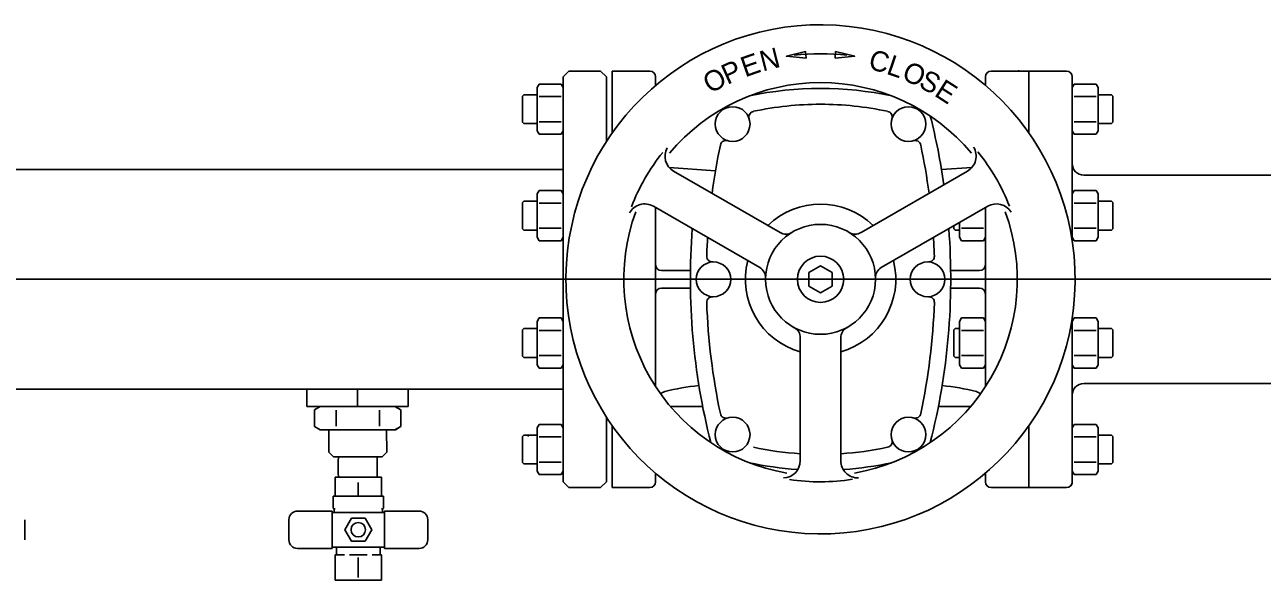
# Model space of a CAD drawing. Extents: x 6710407 to 6714861, y 1868090 to 1871317.
# Drawn here: x 6713875.1 to 6713934, y 1869959.7 to 1869986.1 of the extents above; entities that cross this region are included whole.
import ezdxf

# ---------------------------------------------------------------- set-up
doc = ezdxf.new("R2010")
doc.units = 0
doc.layers.add('Nongeo Data(60)', color=7, linetype='Continuous')

msp = doc.modelspace()

# ---------------------------------------------------------------- linework, layer by layer
at = {"layer": 'Nongeo Data(60)'}
for p, q in [((6713900.993, 1869983.89), (6713900.717, 1869983.614)), ((6713900.717, 1869983.614), (6713900.717, 1869979.484)), ((6713902.507, 1869983.89), (6713900.993, 1869983.89)), ((6713902.507, 1869983.89), (6713902.782, 1869983.614)), ((6713902.782, 1869980.534), (6713902.782, 1869983.614)), ((6713903.057, 1869983.89), (6713904.847, 1869983.89)), ((6713903.057, 1869980.943), (6713903.057, 1869983.89)), ((6713903.057, 1869983.89), (6713903.057, 1869980.943)), ((6713905.122, 1869983.207), (6713905.122, 1869983.614)), ((6713920.816, 1869983.614), (6713920.816, 1869983.207)), ((6713922.364, 1869983.891), (6713921.091, 1869983.891)), ((6713922.881, 1869983.89), (6713921.091, 1869983.89)), ((6713922.881, 1869983.89), (6713922.881, 1869980.943)), ((6713922.881, 1869983.89), (6713922.881, 1869980.943)), ((6713922.881, 1869983.89), (6713924.67, 1869983.89)), ((6713924.946, 1869983.614), (6713924.946, 1869975.799)), ((6713899.576, 1869983.268), (6713899.484, 1869983.108)), ((6713899.484, 1869981.043), (6713899.484, 1869983.108)), ((6713899.576, 1869983.268), (6713900.625, 1869983.268)), ((6713900.625, 1869983.268), (6713900.717, 1869983.108)), ((6713900.717, 1869981.043), (6713900.717, 1869983.108)), ((6713920.816, 1869983.268), (6713920.744, 1869983.268)), ((6713925.038, 1869983.268), (6713924.946, 1869983.108)), ((6713924.946, 1869983.108), (6713924.946, 1869981.043)), ((6713926.087, 1869983.268), (6713925.038, 1869983.268)), ((6713926.087, 1869983.268), (6713926.179, 1869983.108)), ((6713926.179, 1869983.108), (6713926.179, 1869981.043)), ((6713898.79, 1869982.698), (6713898.856, 1869982.764)), ((6713898.79, 1869981.453), (6713898.79, 1869982.698)), ((6713898.856, 1869982.764), (6713899.484, 1869982.764)), ((6713899.579, 1869982.672), (6713900.622, 1869982.672)), ((6713926.084, 1869982.672), (6713925.04, 1869982.672)), ((6713926.806, 1869982.764), (6713926.179, 1869982.764)), ((6713926.873, 1869982.698), (6713926.806, 1869982.764)), ((6713926.873, 1869982.698), (6713926.873, 1869981.453)), ((6713898.79, 1869981.453), (6713898.856, 1869981.387)), ((6713898.856, 1869981.387), (6713899.484, 1869981.387)), ((6713899.579, 1869981.48), (6713900.622, 1869981.48)), ((6713926.084, 1869981.48), (6713925.04, 1869981.48)), ((6713926.806, 1869981.387), (6713926.179, 1869981.387)), ((6713926.873, 1869981.453), (6713926.806, 1869981.387)), ((6713899.576, 1869980.883), (6713899.484, 1869981.043)), ((6713899.576, 1869980.883), (6713900.625, 1869980.883)), ((6713900.625, 1869980.883), (6713900.717, 1869981.043)), ((6713925.038, 1869980.883), (6713924.946, 1869981.043)), ((6713926.087, 1869980.883), (6713925.038, 1869980.883)), ((6713926.087, 1869980.883), (6713926.179, 1869981.043)), ((6713900.717, 1869973.978), (6713900.717, 1869979.484)), ((6713843.175, 1869979.209), (6713899.454, 1869979.209)), ((6713899.454, 1869979.209), (6713900.717, 1869979.209)), ((6713907.969, 1869979.148), (6713905.767, 1869979.302)), ((6713911.043, 1869976.203), (6713905.98, 1869979.126)), ((6713914.895, 1869976.203), (6713919.958, 1869979.126)), ((6713918.728, 1869979.201), (6713920.171, 1869979.302)), ((6713925.496, 1869978.934), (6713931.613, 1869978.934)), ((6713931.613, 1869978.934), (6713949.736, 1869978.934)), ((6713898.79, 1869977.632), (6713898.856, 1869977.698)), ((6713898.79, 1869976.387), (6713898.79, 1869977.632)), ((6713898.856, 1869977.698), (6713899.484, 1869977.698)), ((6713899.576, 1869978.202), (6713899.484, 1869978.042)), ((6713899.484, 1869975.977), (6713899.484, 1869978.042)), ((6713899.576, 1869978.202), (6713900.625, 1869978.202)), ((6713900.625, 1869978.202), (6713900.717, 1869978.042)), ((6713900.717, 1869975.977), (6713900.717, 1869978.042)), ((6713925.038, 1869978.202), (6713924.946, 1869978.042)), ((6713924.946, 1869978.042), (6713924.946, 1869975.977)), ((6713926.087, 1869978.202), (6713925.038, 1869978.202)), ((6713926.087, 1869978.202), (6713926.179, 1869978.042)), ((6713926.179, 1869978.042), (6713926.179, 1869975.977)), ((6713926.806, 1869977.698), (6713926.179, 1869977.698)), ((6713926.873, 1869977.632), (6713926.806, 1869977.698)), ((6713926.873, 1869977.632), (6713926.873, 1869976.387)), ((6713899.579, 1869977.606), (6713900.622, 1869977.606)), ((6713910.079, 1869974.534), (6713905.016, 1869977.457)), ((6713905.122, 1869968.873), (6713905.122, 1869977.396)), ((6713915.859, 1869974.534), (6713920.922, 1869977.457)), ((6713920.816, 1869968.873), (6713920.816, 1869977.396)), ((6713920.816, 1869975.977), (6713920.816, 1869977.396)), ((6713926.084, 1869977.606), (6713925.04, 1869977.606)), ((6713919.307, 1869976.387), (6713919.307, 1869976.524)), ((6713919.582, 1869975.977), (6713919.582, 1869976.683)), ((6713898.79, 1869976.387), (6713898.856, 1869976.321)), ((6713898.856, 1869976.321), (6713899.484, 1869976.321)), ((6713899.576, 1869975.817), (6713899.484, 1869975.977)), ((6713899.579, 1869976.414), (6713900.622, 1869976.414)), ((6713900.625, 1869975.817), (6713900.717, 1869975.977)), ((6713919.307, 1869976.387), (6713919.373, 1869976.321)), ((6713919.373, 1869976.321), (6713919.582, 1869976.321)), ((6713919.675, 1869975.817), (6713919.582, 1869975.977)), ((6713919.677, 1869976.413), (6713920.721, 1869976.413)), ((6713920.723, 1869975.817), (6713920.816, 1869975.977)), ((6713925.038, 1869975.817), (6713924.946, 1869975.977)), ((6713926.084, 1869976.414), (6713925.04, 1869976.414)), ((6713926.087, 1869975.817), (6713926.179, 1869975.977)), ((6713926.806, 1869976.321), (6713926.179, 1869976.321)), ((6713926.873, 1869976.387), (6713926.806, 1869976.321)), ((6713899.576, 1869975.817), (6713900.625, 1869975.817)), ((6713919.675, 1869975.817), (6713920.723, 1869975.817)), ((6713926.087, 1869975.817), (6713925.038, 1869975.817)), ((6713906.777, 1869974.391), (6713905.398, 1869974.391)), ((6713919.161, 1869974.391), (6713920.54, 1869974.391)), ((6713748.2, 1869973.985), (6713995.625, 1869973.985)), ((6713900.717, 1869964.342), (6713900.717, 1869973.978)), ((6713906.777, 1869973.565), (6713905.398, 1869973.565)), ((6713919.161, 1869973.565), (6713920.54, 1869973.565)), ((6713899.576, 1869972.139), (6713899.484, 1869971.979)), ((6713899.484, 1869969.914), (6713899.484, 1869971.979)), ((6713899.576, 1869972.139), (6713900.625, 1869972.139)), ((6713900.625, 1869972.139), (6713900.717, 1869971.979)), ((6713900.717, 1869969.914), (6713900.717, 1869971.979)), ((6713919.675, 1869972.139), (6713919.582, 1869971.979)), ((6713919.582, 1869971.979), (6713919.582, 1869969.914)), ((6713919.675, 1869972.139), (6713920.723, 1869972.139)), ((6713920.723, 1869972.139), (6713920.816, 1869971.979)), ((6713920.816, 1869971.979), (6713920.816, 1869969.914)), ((6713924.946, 1869972.157), (6713924.946, 1869964.342)), ((6713925.038, 1869972.139), (6713924.946, 1869971.979)), ((6713924.946, 1869971.979), (6713924.946, 1869969.914)), ((6713926.087, 1869972.139), (6713925.038, 1869972.139)), ((6713926.087, 1869972.139), (6713926.179, 1869971.979)), ((6713926.179, 1869971.979), (6713926.179, 1869969.914)), ((6713898.79, 1869971.569), (6713898.856, 1869971.635)), ((6713898.79, 1869970.324), (6713898.79, 1869971.569)), ((6713898.856, 1869971.635), (6713899.484, 1869971.635)), ((6713899.579, 1869971.542), (6713900.622, 1869971.542)), ((6713912.005, 1869971.197), (6713912.005, 1869965.351)), ((6713913.933, 1869971.197), (6713913.933, 1869965.351)), ((6713919.307, 1869971.569), (6713919.373, 1869971.635)), ((6713919.307, 1869971.569), (6713919.307, 1869970.324)), ((6713919.373, 1869971.635), (6713919.582, 1869971.635)), ((6713919.677, 1869971.542), (6713920.721, 1869971.542)), ((6713926.084, 1869971.542), (6713925.04, 1869971.542)), ((6713926.806, 1869971.635), (6713926.179, 1869971.635)), ((6713926.873, 1869971.568), (6713926.806, 1869971.635)), ((6713926.873, 1869971.568), (6713926.873, 1869970.324)), ((6713898.79, 1869970.324), (6713898.856, 1869970.258)), ((6713898.856, 1869970.258), (6713899.484, 1869970.258)), ((6713899.579, 1869970.35), (6713900.622, 1869970.35)), ((6713919.307, 1869970.324), (6713919.373, 1869970.258)), ((6713919.373, 1869970.258), (6713919.582, 1869970.258)), ((6713919.677, 1869970.35), (6713920.721, 1869970.35)), ((6713926.084, 1869970.35), (6713925.04, 1869970.35)), ((6713926.806, 1869970.258), (6713926.179, 1869970.258)), ((6713926.873, 1869970.324), (6713926.806, 1869970.258)), ((6713899.576, 1869969.754), (6713899.484, 1869969.914)), ((6713899.576, 1869969.754), (6713900.625, 1869969.754)), ((6713900.625, 1869969.754), (6713900.717, 1869969.914)), ((6713919.675, 1869969.754), (6713919.582, 1869969.914)), ((6713919.675, 1869969.754), (6713920.723, 1869969.754)), ((6713920.723, 1869969.754), (6713920.816, 1869969.914)), ((6713925.038, 1869969.754), (6713924.946, 1869969.914)), ((6713926.087, 1869969.754), (6713925.038, 1869969.754)), ((6713926.087, 1869969.754), (6713926.179, 1869969.914)), ((6713925.496, 1869969.022), (6713931.613, 1869969.022)), ((6713931.613, 1869969.022), (6713949.736, 1869969.022)), ((6713843.175, 1869968.747), (6713899.454, 1869968.747)), ((6713888.532, 1869967.921), (6713888.532, 1869968.747)), ((6713890.941, 1869967.921), (6713890.941, 1869968.747)), ((6713893.35, 1869967.921), (6713893.35, 1869968.747)), ((6713899.454, 1869968.747), (6713900.717, 1869968.747)), ((6713888.532, 1869967.921), (6713893.35, 1869967.921)), ((6713888.884, 1869967.761), (6713889.161, 1869967.921)), ((6713888.884, 1869967.761), (6713888.884, 1869966.98)), ((6713889.917, 1869967.757), (6713889.917, 1869966.984)), ((6713891.983, 1869967.757), (6713891.983, 1869966.984)), ((6713892.998, 1869967.761), (6713892.721, 1869967.921)), ((6713892.998, 1869967.761), (6713892.998, 1869966.98)), ((6713907.362, 1869967.921), (6713905.832, 1869967.921)), ((6713918.576, 1869967.921), (6713920.106, 1869967.921)), ((6713899.576, 1869967.072), (6713899.484, 1869966.913)), ((6713899.576, 1869967.072), (6713900.625, 1869967.072)), ((6713900.625, 1869967.072), (6713900.717, 1869966.913)), ((6713902.782, 1869967.422), (6713902.782, 1869964.342)), ((6713925.038, 1869967.072), (6713924.946, 1869966.912)), ((6713926.087, 1869967.072), (6713925.038, 1869967.072)), ((6713926.087, 1869967.072), (6713926.179, 1869966.912)), ((6713888.884, 1869966.98), (6713889.161, 1869966.82)), ((6713889.161, 1869966.82), (6713892.739, 1869966.82)), ((6713889.161, 1869966.82), (6713892.739, 1869966.82)), ((6713889.575, 1869965.75), (6713889.575, 1869966.82)), ((6713892.326, 1869965.75), (6713892.325, 1869966.82)), ((6713892.998, 1869966.98), (6713892.721, 1869966.82)), ((6713892.868, 1869966.894), (6713892.739, 1869966.82)), ((6713898.79, 1869966.503), (6713898.856, 1869966.569)), ((6713898.79, 1869965.258), (6713898.79, 1869966.503)), ((6713898.856, 1869966.569), (6713899.484, 1869966.569)), ((6713899.044, 1869966.503), (6713899.111, 1869966.569)), ((6713899.484, 1869964.848), (6713899.484, 1869966.913)), ((6713899.579, 1869966.476), (6713900.622, 1869966.476)), ((6713900.717, 1869964.848), (6713900.717, 1869966.913)), ((6713903.057, 1869964.066), (6713903.057, 1869967.013)), ((6713903.057, 1869967.013), (6713903.057, 1869964.066)), ((6713922.881, 1869967.013), (6713922.881, 1869964.066)), ((6713922.881, 1869967.013), (6713922.881, 1869964.066)), ((6713924.946, 1869966.912), (6713924.946, 1869964.848)), ((6713926.084, 1869966.476), (6713925.04, 1869966.476)), ((6713926.179, 1869966.912), (6713926.179, 1869964.848)), ((6713926.806, 1869966.569), (6713926.179, 1869966.569)), ((6713926.873, 1869966.502), (6713926.806, 1869966.569)), ((6713926.873, 1869966.502), (6713926.873, 1869965.258)), ((6713889.794, 1869965.531), (6713889.575, 1869965.75)), ((6713889.794, 1869965.531), (6713892.107, 1869965.531)), ((6713890.025, 1869965.325), (6713890.031, 1869965.531)), ((6713890.025, 1869964.774), (6713890.025, 1869965.325)), ((6713891.875, 1869965.325), (6713891.869, 1869965.531)), ((6713891.875, 1869964.774), (6713891.875, 1869965.325)), ((6713892.107, 1869965.531), (6713892.326, 1869965.75)), ((6713899.579, 1869965.284), (6713900.622, 1869965.284)), ((6713926.084, 1869965.284), (6713925.04, 1869965.284)), ((6713890.025, 1869964.774), (6713890.031, 1869964.567)), ((6713891.875, 1869964.774), (6713891.869, 1869964.567)), ((6713898.79, 1869965.258), (6713898.856, 1869965.192)), ((6713898.856, 1869965.192), (6713899.484, 1869965.192)), ((6713899.576, 1869964.688), (6713899.484, 1869964.848)), ((6713899.576, 1869964.688), (6713900.625, 1869964.688)), ((6713900.625, 1869964.688), (6713900.717, 1869964.848)), ((6713905.122, 1869964.342), (6713905.122, 1869964.749)), ((6713920.816, 1869964.688), (6713920.744, 1869964.688)), ((6713920.816, 1869964.342), (6713920.816, 1869964.749)), ((6713925.038, 1869964.688), (6713924.946, 1869964.848)), ((6713926.087, 1869964.688), (6713925.038, 1869964.688)), ((6713926.087, 1869964.688), (6713926.179, 1869964.848)), ((6713926.806, 1869965.192), (6713926.179, 1869965.192)), ((6713926.873, 1869965.258), (6713926.806, 1869965.192)), ((6713890.977, 1869964.567), (6713889.876, 1869964.567)), ((6713889.876, 1869963.664), (6713889.876, 1869964.567)), ((6713889.919, 1869964.456), (6713889.919, 1869964.456)), ((6713890.977, 1869964.567), (6713892.078, 1869964.567)), ((6713890.977, 1869964.316), (6713890.977, 1869963.664)), ((6713891.769, 1869964.456), (6713891.769, 1869964.456)), ((6713892.078, 1869963.664), (6713892.078, 1869964.567)), ((6713900.993, 1869964.066), (6713900.717, 1869964.342)), ((6713902.782, 1869964.342), (6713902.507, 1869964.066)), ((6713892.179, 1869963.664), (6713889.776, 1869963.664)), ((6713889.776, 1869963.664), (6713889.776, 1869963.112)), ((6713892.078, 1869963.664), (6713892.078, 1869963.805)), ((6713892.179, 1869963.664), (6713892.179, 1869963.112)), ((6713902.507, 1869964.066), (6713900.993, 1869964.066)), ((6713903.057, 1869964.066), (6713904.847, 1869964.066)), ((6713922.881, 1869964.066), (6713921.091, 1869964.066)), ((6713922.881, 1869964.066), (6713924.67, 1869964.066)), ((6713889.738, 1869962.954), (6713888.086, 1869962.954)), ((6713889.738, 1869962.062), (6713889.738, 1869962.954)), ((6713889.876, 1869963.063), (6713889.81, 1869963.063)), ((6713889.828, 1869963.026), (6713889.828, 1869962.888)), ((6713892.078, 1869963.063), (6713892.144, 1869963.063)), ((6713892.126, 1869963.026), (6713892.126, 1869962.888)), ((6713892.179, 1869963.063), (6713892.179, 1869963.063)), ((6713892.216, 1869962.954), (6713893.868, 1869962.954)), ((6713892.216, 1869962.062), (6713892.216, 1869962.954)), ((6713875.106, 1869962.062), (6713875.106, 1869962.541)), ((6713887.673, 1869962.062), (6713887.673, 1869962.541)), ((6713890.977, 1869962.888), (6713889.738, 1869962.888)), ((6713890.977, 1869962.888), (6713892.216, 1869962.888)), ((6713894.281, 1869962.062), (6713894.281, 1869962.541)), ((6713875.106, 1869962.062), (6713875.106, 1869961.583)), ((6713887.673, 1869962.062), (6713887.673, 1869961.583)), ((6713889.738, 1869962.062), (6713889.738, 1869961.17)), ((6713892.216, 1869962.062), (6713892.216, 1869961.17)), ((6713894.281, 1869962.062), (6713894.281, 1869961.583)), ((6713889.738, 1869961.17), (6713888.086, 1869961.17)), ((6713890.977, 1869961.236), (6713889.738, 1869961.236)), ((6713889.945, 1869961.226), (6713889.945, 1869960.911)), ((6713890.977, 1869961.236), (6713892.216, 1869961.236)), ((6713892.01, 1869961.226), (6713892.01, 1869960.911)), ((6713892.216, 1869961.17), (6713893.868, 1869961.17)), ((6713890.326, 1869960.876), (6713889.876, 1869960.876)), ((6713889.876, 1869960.876), (6713889.876, 1869959.659)), ((6713890.977, 1869960.876), (6713890.551, 1869960.876)), ((6713890.977, 1869960.876), (6713891.403, 1869960.876)), ((6713890.977, 1869959.787), (6713890.977, 1869960.748)), ((6713891.628, 1869960.876), (6713892.078, 1869960.876)), ((6713892.078, 1869960.876), (6713892.078, 1869959.659)), ((6713890.977, 1869959.659), (6713889.876, 1869959.659)), ((6713892.078, 1869959.659), (6713890.977, 1869959.659))]:
    msp.add_line(p, q, dxfattribs=at)
for points in [[(6713912.281, 1869984.507), (6713912.257, 1869984.816), (6713911.342, 1869984.592)], [(6713913.658, 1869984.507), (6713913.681, 1869984.816), (6713914.596, 1869984.592)], [(6713913.52, 1869974.296), (6713912.969, 1869974.614), (6713912.418, 1869974.296), (6713912.418, 1869973.66), (6713912.969, 1869973.342), (6713913.52, 1869973.66)], [(6713890.659, 1869962.612), (6713890.341, 1869962.062), (6713890.659, 1869961.511), (6713891.295, 1869961.511), (6713891.613, 1869962.062), (6713891.295, 1869962.612)]]:
    msp.add_lwpolyline(points, close=True, dxfattribs=at)
for centre, radius in [((6713908.787, 1869981.368), 0.826), ((6713917.151, 1869981.368), 0.826), ((6713912.969, 1869973.978), 2.616), ((6713907.876, 1869973.978), 0.826), ((6713912.969, 1869973.978), 1.101), ((6713918.063, 1869973.978), 0.826), ((6713908.787, 1869966.588), 0.826), ((6713917.151, 1869966.588), 0.826), ((6713890.977, 1869962.062), 0.344)]:
    msp.add_circle(centre, radius, dxfattribs=at)
for centre, radius, start, end in [((6713912.969, 1869973.978), 12.114, 359.41089, 359.36318), ((6713912.969, 1869973.978), 10.738, 83.28613, 96.71387), ((6713904.847, 1869983.614), 0.275, 0, 90), ((6713921.091, 1869983.614), 0.275, 90, 180), ((6713922.364, 1869984.166), 0.275, 270, 281.76829), ((6713924.67, 1869983.614), 0.275, 0, 90), ((6713912.969, 1869973.978), 9.361, 39.89685, 140.10315), ((6713912.969, 1869966.946), 16.118, 77.84886, 102.15114), ((6713909.836, 1869981.702), 0.275, 101.98605, 197.65954), ((6713912.969, 1869966.946), 15.361, 90, 101.98605), ((6713912.969, 1869966.946), 15.361, 78.01395, 90), ((6713916.102, 1869981.702), 0.275, 342.34046, 78.01395), ((6713887.639, 1869973.978), 31.524, 8.21165, 14.26664), ((6713908.472, 1869980.313), 0.275, 73.39256, 168.00918), ((6713917.466, 1869980.313), 0.275, 11.99082, 106.60744), ((6713912.969, 1869973.978), 9.636, 141.17332, 159.04595), ((6713906.393, 1869979.841), 0.826, 151.79151, 240), ((6713938.299, 1869973.978), 30.767, 168.00918, 172.35308), ((6713887.639, 1869973.978), 30.767, 7.64692, 11.99082), ((6713919.545, 1869979.841), 0.826, 300, 31.31351), ((6713912.969, 1869973.978), 9.636, 21.17332, 39.04595), ((6713925.496, 1869979.484), 0.551, 180, 270), ((6713912.969, 1869973.978), 9.361, 159.89685, 260.10315), ((6713904.603, 1869976.741), 0.826, 60, 151.31351), ((6713912.969, 1869973.978), 3.579, 45.6185, 134.3815), ((6713912.969, 1869973.978), 9.361, 279.89685, 20.10315), ((6713921.335, 1869976.741), 0.826, 31.79151, 120), ((6713938.299, 1869973.978), 31.524, 175.61453, 194.26664), ((6713938.299, 1869973.978), 30.767, 176.29245, 177.93223), ((6713911.318, 1869976.68), 0.551, 240, 301.42812), ((6713914.62, 1869976.68), 0.551, 238.57188, 300), ((6713887.639, 1869973.978), 31.524, 345.73336, 4.38547), ((6713887.639, 1869973.978), 30.767, 2.06778, 3.70755), ((6713907.827, 1869975.078), 0.275, 177.93223, 272.54885), ((6713912.969, 1869973.978), 3.579, 165.6185, 254.3815), ((6713912.969, 1869973.978), 3.579, 285.6185, 14.3815), ((6713918.112, 1869975.078), 0.275, 267.45115, 2.06778), ((6713905.398, 1869974.666), 0.275, 180, 270), ((6713909.804, 1869974.057), 0.551, 358.57188, 60), ((6713916.134, 1869974.057), 0.551, 120, 181.42812), ((6713920.54, 1869974.666), 0.275, 270, 0), ((6713905.398, 1869973.29), 0.275, 90, 180), ((6713920.54, 1869973.29), 0.275, 0, 90), ((6713907.827, 1869972.878), 0.275, 87.45115, 182.06778), ((6713918.112, 1869972.878), 0.275, 357.93223, 92.54885), ((6713938.299, 1869973.978), 30.767, 182.06778, 191.99082), ((6713887.639, 1869973.978), 30.767, 348.00918, 357.93223), ((6713911.455, 1869971.197), 0.551, 0, 61.42812), ((6713914.483, 1869971.197), 0.551, 118.57188, 180), ((6713908.261, 1869958.231), 10.748, 95.76035, 104.57611), ((6713917.678, 1869958.231), 10.748, 75.42389, 84.23965), ((6713925.496, 1869968.472), 0.551, 90, 180), ((6713905.838, 1869967.729), 0.948, 107.31382, 121.04157), ((6713920.1, 1869967.729), 0.948, 58.95843, 72.68618), ((6713908.472, 1869967.643), 0.275, 191.99082, 286.60744), ((6713917.466, 1869967.643), 0.275, 253.39256, 348.00918), ((6713912.969, 1869981.01), 15.361, 258.01395, 266.40328), ((6713912.969, 1869981.01), 15.361, 273.59672, 281.98605), ((6713916.102, 1869966.254), 0.275, 281.98605, 17.65954), ((6713911.179, 1869965.351), 0.826, 271.79151, 0), ((6713914.759, 1869965.351), 0.826, 180, 271.31351), ((6713912.969, 1869981.01), 16.118, 257.84886, 266.06847), ((6713912.969, 1869981.01), 16.118, 273.93153, 282.15114), ((6713904.847, 1869964.342), 0.275, 270, 0), ((6713912.969, 1869973.978), 9.636, 261.17332, 279.04595), ((6713921.091, 1869964.342), 0.275, 180, 270), ((6713924.67, 1869964.342), 0.275, 270, 0), ((6713924.67, 1869964.342), 0.275, 309.95872, 0), ((6713888.086, 1869962.541), 0.413, 90, 180), ((6713889.824, 1869963.112), 0.0481, 180, 242.72039), ((6713889.78, 1869963.026), 0.0481, 0, 62.72039), ((6713892.175, 1869963.026), 0.0481, 117.27961, 180), ((6713892.13, 1869963.112), 0.0481, 297.27961, 0), ((6713893.868, 1869962.541), 0.413, 0, 90), ((6713888.086, 1869961.583), 0.413, 180, 270), ((6713892.044, 1869961.226), 0.0344, 164.17334, 180), ((6713893.868, 1869961.583), 0.413, 270, 0), ((6713889.91, 1869960.911), 0.0344, 270, 0), ((6713892.044, 1869960.911), 0.0344, 180, 270)]:
    msp.add_arc(centre, radius, start, end, dxfattribs=at)

# ---------------------------------------------------------------- texts
for s, rotation, p in [('E', 19.33908, (6713909.38, 1869983.584)), ('N', 14.33908, (6713910.215, 1869983.866)), ('C', 346.07317, (6713915.201, 1869983.996)), ('P', 24.33908, (6713908.534, 1869983.226)), ('L', 341.38567, (6713916.057, 1869983.768)), ('O', 336.69817, (6713916.783, 1869983.508)), ('O', 29.33908, (6713907.722, 1869982.792)), ('S', 332.01067, (6713917.585, 1869983.15)), ('E', 327.32317, (6713918.333, 1869982.738))]:
    msp.add_text(s, height=0.964, rotation=rotation, dxfattribs=at).set_placement(p)

doc.saveas('drawing.dxf')
